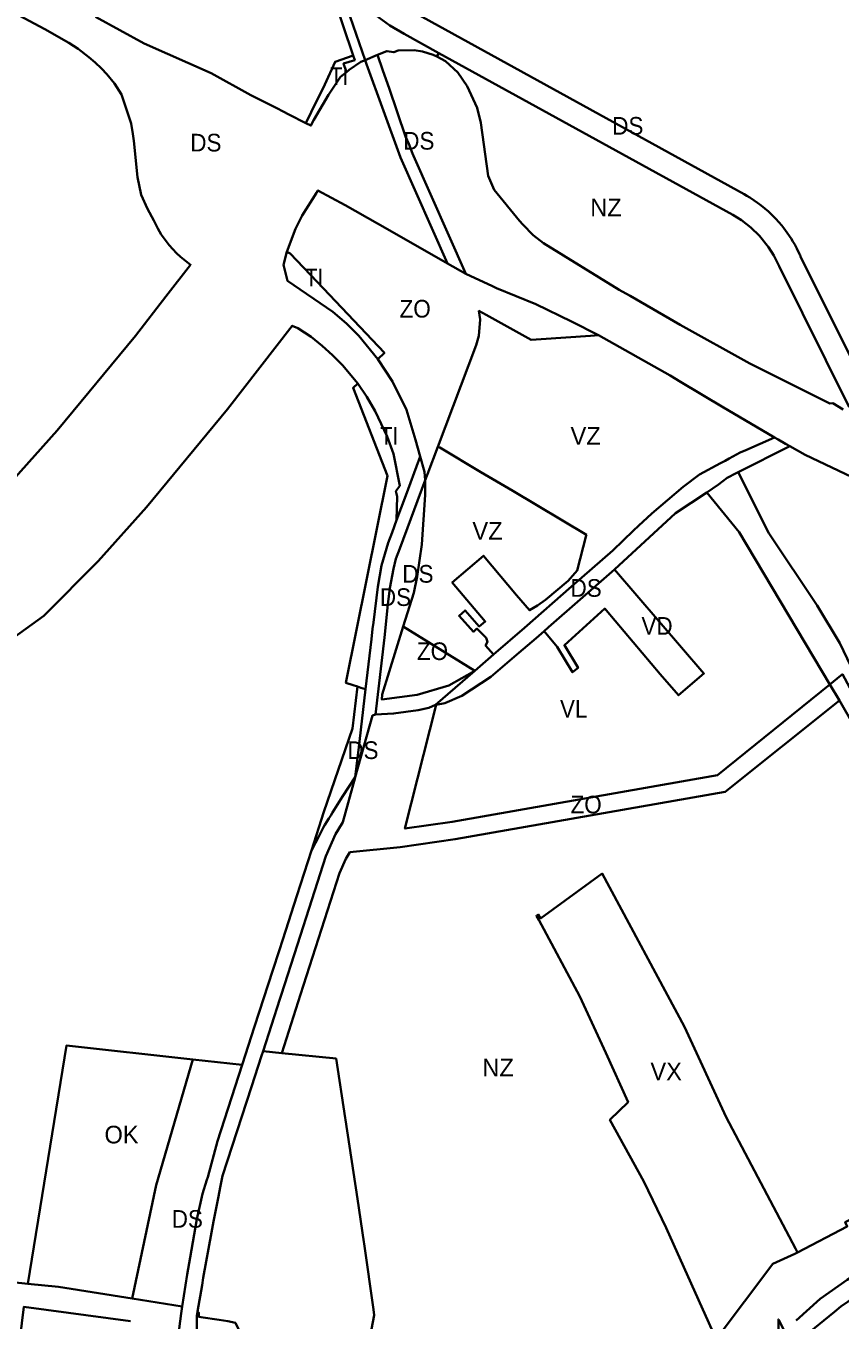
# Model space of a CAD drawing. Extents: x -650451 to -642268, y -1075216 to -1066610.
# Drawn here: x -646844 to -646153, y -1069586 to -1068487 of the extents above; entities that cross this region are included whole.
import ezdxf

# ---------------------------------------------------------------- set-up
doc = ezdxf.new("R2010")
doc.units = 0
doc.header["$LTSCALE"] = 6
doc.layers.add('1', color=7, linetype='Continuous', lineweight=35)
doc.layers.add('2', color=7, linetype='Continuous')
doc.layers.add('3', color=7, linetype='Continuous')

msp = doc.modelspace()

# ---------------------------------------------------------------- linework, layer by layer
at = {"layer": '1'}
for p, q in [((-646545.57, -1068511.42), (-646556.22, -1068515.84)), ((-646495.416, -1068512.888), (-646493.511, -1068509.855)), ((-646470.65, -1068697.38), (-646486.23, -1068688.54)), ((-646195.52, -1068843.92), (-646239.43, -1068865.79)), ((-646462.98, -1069034.61), (-646524, -1068997)), ((-646153.307, -1069059.947), (-646161.484, -1069046.228)), ((-646153.307, -1069059.947), (-646025.14, -1069285.394)), ((-646495.89, -1069063.531), (-646496.317, -1069063.61)), ((-646642.89, -1069357.68), (-646626.774, -1069359.349)), ((-646702.425, -1069364.771), (-646660.526, -1069369.36)), ((-646711.442, -1069574.759), (-646754.066, -1069567.993))]:
    msp.add_line(p, q, dxfattribs=at)
for points in [[(-646773.65, -1067792.47), (-646774.2, -1067796.04), (-646763.68, -1067804.12), (-646770.85, -1067872.24), (-646732.3, -1067997.18), (-646706.52, -1068080.45), (-646686.65, -1068143.62), (-646653.73, -1068249.25), (-646633.16, -1068315.26), (-646608.14, -1068389.1), (-646595.67, -1068425.48), (-646583.64, -1068460.55), (-646566.33, -1068512.04)], [(-646556.22, -1068515.84), (-646568.87, -1068479.14), (-646576.4, -1068457.27), (-646588.07, -1068422.96)], [(-646493.511, -1068509.855), (-646523.105, -1068493.54), (-646535.245, -1068486.342), (-646544.525, -1068479.79), (-646553.677, -1068472.283), (-646561.544, -1068464.842)], [(-646854.18, -1068475.8), (-646828.2, -1068489.61), (-646807.82, -1068501.17), (-646799.79, -1068506.39), (-646790.66, -1068513.24), (-646785.34, -1068517.77), (-646779.93, -1068522.9), (-646775.44, -1068527.74), (-646768.95, -1068535.8), (-646763.1, -1068545.18), (-646754.92, -1068569.81), (-646753.35, -1068578.6), (-646752.59, -1068584.55), (-646749.35, -1068615.18), (-646746.32, -1068630.23), (-646740.91, -1068642.34), (-646735.62, -1068652.21), (-646732.25, -1068659.06), (-646729.34, -1068663.94), (-646722.6, -1068673.11), (-646716.39, -1068679.8), (-646712.93, -1068683), (-646704.316, -1068689.698), (-646725.374, -1068716.786), (-646751.116, -1068749.975), (-646817.718, -1068830.545), (-646855.506, -1068872.883)], [(-646606.59, -1068569.33), (-646620.94, -1068561.96), (-646625.86, -1068559.47), (-646631.18, -1068556.77), (-646653.21, -1068545.58), (-646686.84, -1068526.89), (-646743.69, -1068501.76), (-646785.05, -1068479.12)], [(-646126.317, -1068803.654), (-646186.371, -1068682.825), (-646186.901, -1068681.614), (-646187.091, -1068681.19), (-646189.676, -1068675.819), (-646191.425, -1068672.562), (-646192.895, -1068670.012), (-646194.492, -1068667.409), (-646195.834, -1068665.339), (-646197.683, -1068662.645), (-646199.218, -1068660.531), (-646200.727, -1068658.552), (-646202.389, -1068656.475), (-646204.769, -1068653.669), (-646207.455, -1068650.718), (-646209.607, -1068648.501), (-646213.784, -1068644.532), (-646216.809, -1068641.902), (-646219.751, -1068639.522), (-646222.933, -1068637.129), (-646225.838, -1068635.097), (-646229.573, -1068632.68), (-646232.141, -1068631.139), (-646234.342, -1068629.892), (-646513.45, -1068476.025)], [(-646606.59, -1068569.33), (-646602.01, -1068560.15), (-646590.31, -1068536.69), (-646581.64, -1068517.24), (-646566.33, -1068512.04)], [(-646572.02, -1068526.07), (-646574.48, -1068518.75), (-646565.04, -1068515.86), (-646566.33, -1068512.04)], [(-646495.416, -1068512.888), (-646498.48, -1068511.26), (-646507.4, -1068508.45), (-646514.39, -1068507.56), (-646528.18, -1068507.58), (-646531.9, -1068509.25), (-646537.71, -1068508.16), (-646545.57, -1068511.42)], [(-646545.57, -1068511.42), (-646541.06, -1068524.58), (-646535.84, -1068539.8), (-646521.81, -1068580.69), (-646519.14, -1068587.06), (-646516.07, -1068595.08), (-646515.09, -1068597.29), (-646470.65, -1068697.38)], [(-646495.416, -1068512.888), (-646487.92, -1068516.87), (-646477.41, -1068526.45), (-646469.51, -1068538.15), (-646461.14, -1068556.34), (-646458.03, -1068569.26), (-646451.82, -1068614.31), (-646446.54, -1068626.14), (-646425.11, -1068652.37), (-646422.32, -1068655.58), (-646413.45, -1068664.71), (-646404.83, -1068671.52), (-646340.36, -1068710.915), (-646337.93, -1068712.4), (-646331.26, -1068716.25), (-646288.59, -1068740.88), (-646229.44, -1068773.53), (-646161.45, -1068807.54), (-646159.1, -1068807.43), (-646150.26, -1068812.81)], [(-646145.083, -1068810.83), (-646204.654, -1068690.937), (-646209.179, -1068681.795), (-646213.659, -1068674.696), (-646221.348, -1068665.144), (-646228.691, -1068658.051), (-646236.707, -1068651.891), (-646243.997, -1068647.407), (-646493.511, -1068509.855)], [(-646556.22, -1068515.84), (-646559.72, -1068517.29), (-646569.61, -1068524.1), (-646572.02, -1068526.07)], [(-646486.23, -1068688.54), (-646526.1, -1068598.55), (-646555, -1068519.38), (-646556.22, -1068515.84)], [(-646572.02, -1068526.07), (-646577.07, -1068530.2), (-646587.28, -1068545.28), (-646599.75, -1068566.49), (-646602.21, -1068571.5), (-646606.59, -1068569.33)], [(-646622.68, -1068678.75), (-646615.19, -1068659.11), (-646609.7, -1068647.84), (-646597.4, -1068628.74), (-646596.28, -1068626.52), (-646573.14, -1068638.98), (-646545.73, -1068654.81), (-646501.64, -1068679.81), (-646486.23, -1068688.54)], [(-646545.32, -1068769.89), (-646561.5, -1068750.22), (-646571.91, -1068739.54), (-646583.49, -1068729.76), (-646622.01, -1068703.3), (-646625.35, -1068689.7), (-646622.68, -1068678.75)], [(-646622.68, -1068678.75), (-646619.74, -1068680.15), (-646596.93, -1068704.15), (-646539.78, -1068764.65), (-646545.32, -1068769.89)], [(-646357.87, -1068749.64), (-646380.94, -1068737.81), (-646411.3, -1068723.11), (-646444.51, -1068709.64), (-646448.02, -1068707.99), (-646470.65, -1068697.38)], [(-646494.52, -1068844.29), (-646461.92, -1068757.93), (-646459.59, -1068750.19), (-646458.57, -1068736.31), (-646459.54, -1068728.94), (-646453.51, -1068732.3), (-646415.3, -1068753.62), (-646406.7, -1068753.03), (-646364.77, -1068750.16), (-646357.87, -1068749.64)], [(-646562.49, -1068790.69), (-646575.28, -1068775.04), (-646583.98, -1068766.42), (-646592.53, -1068758.66), (-646601.86, -1068751.01), (-646613.44, -1068743.65), (-646617.991, -1068741.503), (-646673.05, -1068812.491), (-646741.85, -1068895.719), (-646782.784, -1068941.581), (-646829.104, -1068987.917), (-646880.163, -1069024.903), (-646929.186, -1069052.925), (-646978.92, -1069073.93), (-647065.688, -1069087.73), (-647123.648, -1069091.043), (-647197.498, -1069094.255), (-647270.522, -1069094.255), (-647344.902, -1069091.02), (-647426.417, -1069084.624), (-647511.94, -1069076.703), (-647708.401, -1069056.275), (-647756.441, -1069053.207), (-647798.631, -1069052.508)], [(-646357.87, -1068749.64), (-646297.08, -1068783.8), (-646288.37, -1068789.04), (-646251.73, -1068811.04), (-646214.92, -1068832.85), (-646208.7, -1068836.39)], [(-646545.32, -1068769.89), (-646532.92, -1068788.95), (-646521.18, -1068812.95), (-646513.27, -1068838.37), (-646509.323, -1068852.529)], [(-646562.61, -1069048.08), (-646566.25, -1069046.92), (-646572.42, -1069044.94), (-646537.3, -1068868.95), (-646566.34, -1068794.32), (-646562.49, -1068790.69)], [(-646562.49, -1068790.69), (-646554.8, -1068801.98), (-646547.68, -1068814.22), (-646537.35, -1068835.56), (-646532.16, -1068850.47), (-646526.64, -1068877.47), (-646530.06, -1068882.16), (-646528.92, -1068886.55), (-646529.44, -1068906.81)], [(-646208.7, -1068836.39), (-646232.81, -1068847.24), (-646237.82, -1068849.24), (-646247.14, -1068854.3), (-646250.58, -1068856.16), (-646254.36, -1068858.21), (-646272.13, -1068867.84), (-646286.22, -1068878.44), (-646312.72, -1068901.07), (-646324.04, -1068911.62), (-646328.28, -1068915.58), (-646345.87, -1068932.56), (-646380.88, -1068963.08), (-646420.96, -1068998.03), (-646447.2, -1069020.9)], [(-646208.7, -1068836.39), (-646205.48, -1068838.23), (-646199.24, -1068841.79), (-646195.52, -1068843.92)], [(-646529.44, -1068906.81), (-646521.63, -1068885.74), (-646510.56, -1068855.86), (-646509.323, -1068852.529)], [(-646509.323, -1068852.529), (-646505.69, -1068865.56), (-646505.17, -1068872.78)], [(-646505.17, -1068872.78), (-646503.24, -1068867.61), (-646494.52, -1068844.29)], [(-646494.52, -1068844.29), (-646492.73, -1068845.01), (-646457.86, -1068865.8), (-646430.86, -1068881.89), (-646368.3, -1068919.19), (-646368.42, -1068919.59), (-646376.02, -1068949.34), (-646383.86, -1068958.24), (-646403.13, -1068974.41), (-646409.67, -1068979.3), (-646416.71, -1068983.21), (-646427.77, -1068970.39), (-646455.78, -1068936.87), (-646468.83, -1068948.26), (-646482.2, -1068959.52), (-646454.21, -1068992.73), (-646459.25, -1068996.98), (-646471.24, -1068983.41), (-646476.35, -1068987.98), (-646464.24, -1069001.49), (-646461.29, -1068998.81), (-646453.48, -1069006.75), (-646452.37, -1069010.01), (-646453.88, -1069013.1), (-646447.2, -1069020.9)], [(-646195.52, -1068843.92), (-646182.57, -1068851.3), (-646137.23, -1068872.6)], [(-646505.17, -1068872.78), (-646526.81, -1068930.69), (-646530.08, -1068939.43), (-646532.13, -1068948), (-646535.13, -1068964.38), (-646537.02, -1068978.44), (-646539.77, -1069006.25), (-646547.413, -1069071.71)], [(-646505.17, -1068872.78), (-646505.12, -1068885.31), (-646507.91, -1068927.47), (-646512.07, -1068954.68), (-646514.91, -1068968.48), (-646524, -1068997)], [(-646239.43, -1068865.79), (-646241.07, -1068866.67), (-646248.82, -1068870.79), (-646256.13, -1068876.42), (-646266.118, -1068883.048)], [(-646239.43, -1068865.79), (-646213.25, -1068917.87), (-646172.32, -1068979.11), (-646153.2, -1069011.21), (-646103.59, -1069114.91)], [(-646266.118, -1068883.048), (-646292.75, -1068900.72), (-646344.49, -1068948.736)], [(-646161.484, -1069046.228), (-646238.632, -1068916.799), (-646266.118, -1068883.048)], [(-646555.84, -1069050.22), (-646550.89, -1069007.7), (-646549.81, -1068998.88), (-646549.17, -1068993.71), (-646545.42, -1068963.3), (-646542.16, -1068945.12), (-646536.54, -1068925.95), (-646533.28, -1068917.17), (-646529.44, -1068906.81)], [(-646404.269, -1069001.033), (-646400.39, -1068997.58), (-646344.49, -1068948.736)], [(-646344.49, -1068948.736), (-646268.528, -1069036.82), (-646290.099, -1069055.423), (-646305.65, -1069037.39), (-646351.641, -1068983.083), (-646351.638, -1068983.08), (-646352.71, -1068981.82), (-646386.936, -1069012.936), (-646375.346, -1069032.07), (-646379.973, -1069035.889), (-646393.09, -1069014.234), (-646404.269, -1069001.033)], [(-646524, -1068997), (-646541.71, -1069054.76), (-646542, -1069059), (-646512, -1069055), (-646485, -1069047), (-646462.98, -1069034.61)], [(-646404.269, -1069001.033), (-646410.96, -1069006.99), (-646425.52, -1069019.41), (-646449.419, -1069039.805), (-646474.13, -1069055.83), (-646488.537, -1069062.169), (-646495.89, -1069063.531)], [(-646496.317, -1069063.61), (-646462.98, -1069034.61), (-646447.2, -1069020.9)], [(-646017.15, -1069280.19), (-646037.99, -1069242.88), (-646107, -1069119.41), (-646150.87, -1069037.64), (-646152.26, -1069038.76), (-646161.484, -1069046.228)], [(-646601.82, -1069187.25), (-646591.26, -1069154.54), (-646566.82, -1069083.62), (-646562.61, -1069048.08)], [(-646564.54, -1069125.08), (-646562.35, -1069106.21), (-646561.88, -1069102.18), (-646555.84, -1069050.22)], [(-646562.61, -1069048.08), (-646559.8, -1069048.98), (-646555.84, -1069050.22)], [(-646495.89, -1069063.531), (-646522.35, -1069168.648), (-646482.211, -1069162.813), (-646256.824, -1069123.414), (-646161.484, -1069046.228)], [(-646153.307, -1069059.947), (-646250.409, -1069137.52), (-646479.84, -1069177.626), (-646526.31, -1069184.381), (-646569.114, -1069188.86), (-646572.586, -1069194.485), (-646577.878, -1069206.485), (-646611.107, -1069309.68), (-646626.774, -1069359.349)], [(-646547.413, -1069071.71), (-646549.91, -1069072.542), (-646564.54, -1069125.08)], [(-646496.317, -1069063.61), (-646502, -1069066), (-646511, -1069068), (-646532, -1069071), (-646547.413, -1069071.71)], [(-646564.54, -1069125.08), (-646564.605, -1069125.271), (-646575.015, -1069163.152), (-646575.87, -1069164.54), (-646581.29, -1069173.32), (-646589.56, -1069192.07), (-646601.41, -1069229.34), (-646613.6, -1069267.04), (-646627.59, -1069310.34), (-646628.66, -1069313.66), (-646642.89, -1069357.68)], [(-646564.54, -1069125.08), (-646575.4, -1069141.46), (-646582.46, -1069152.81), (-646583.89, -1069155.1), (-646585.42, -1069157.56), (-646586.97, -1069160.06), (-646590.38, -1069165.55), (-646591.4, -1069167.48), (-646595.32, -1069174.92), (-646601.82, -1069187.25)], [(-646601.82, -1069187.25), (-646614.05, -1069225.78), (-646626.03, -1069262.8), (-646629.14, -1069272.42), (-646634.5, -1069288.96), (-646650.036, -1069336.95), (-646660.526, -1069369.36)], [(-646189.17, -1069528.74), (-646190.68, -1069525.54), (-646249.6, -1069413.93), (-646284.98, -1069337.17), (-646354.82, -1069206.96), (-646407.33, -1069245.03), (-646409.21, -1069241.71), (-646410.74, -1069242.8), (-646408.81, -1069246.1), (-646373.91, -1069311.42), (-646351.69, -1069359.26), (-646332.84, -1069401.02), (-646348.36, -1069416.16), (-646319.61, -1069468.58), (-646300.42, -1069507.93), (-646258.086, -1069602.285)], [(-646702.425, -1069364.771), (-646809.879, -1069353.002), (-646842.441, -1069555.283)], [(-646698.4, -1069578.93), (-646694.47, -1069556.69), (-646693.58, -1069550.28), (-646686.56, -1069511.7), (-646684.95, -1069502.53), (-646680.77, -1069481.22), (-646679.13, -1069473.51), (-646677.18, -1069463.79), (-646652.72, -1069388.08), (-646644.22, -1069361.78), (-646642.89, -1069357.68)], [(-646626.774, -1069359.349), (-646580.797, -1069364.111), (-646573.08, -1069414.47), (-646572.86, -1069416.23), (-646562.65, -1069483.12), (-646557.39, -1069519.61), (-646557.09, -1069521.46), (-646549.097, -1069577.256), (-646548.41, -1069582.03), (-646550.76, -1069593.9), (-646560.5, -1069643.52), (-646569.86, -1069690.67), (-646581.489, -1069759.421)], [(-646702.425, -1069364.771), (-646733.74, -1069471.688), (-646754.066, -1069567.993)], [(-646660.526, -1069369.36), (-646681.5, -1069434.17), (-646689.8, -1069464.71), (-646690.51, -1069466.97), (-646694.26, -1069478.99), (-646699.07, -1069500.57), (-646704.68, -1069533.06), (-646707.16, -1069547.44), (-646711.442, -1069574.759)], [(-646189.17, -1069528.74), (-646146.8, -1069506.6), (-646148.5, -1069503), (-646102.15, -1069479.49), (-646080.35, -1069469.89), (-646028.16, -1069441.58), (-646023.96, -1069440.34)], [(-646017.63, -1069499.08), (-646020.75, -1069500), (-646075.48, -1069516.38), (-646094.39, -1069523.34), (-646112.56, -1069531.78), (-646129.87, -1069541.19), (-646146.81, -1069551.97), (-646169.9, -1069568.04), (-646190.07, -1069586.48)], [(-646265.02, -1069696.43), (-646263.66, -1069694.78), (-646244.03, -1069670.61), (-646232.98, -1069657.69), (-646203.35, -1069617.55), (-646197.52, -1069612.3), (-646186.23, -1069623.04), (-646193.38, -1069608.83), (-646183.24, -1069600.22), (-646157.69, -1069579.08), (-646152.27, -1069574.59), (-646128.27, -1069558.17), (-646091.98, -1069538.88), (-646085.67, -1069536.53), (-646056.24, -1069525.54), (-646018.55, -1069514.14)], [(-647608.81, -1069551.868), (-647567.252, -1069548.083), (-647434.969, -1069537.141), (-647341.697, -1069532.602), (-647204.293, -1069530.647), (-647140.008, -1069530.068), (-647046.325, -1069533.275), (-646986.633, -1069539.757), (-646842.441, -1069555.283)], [(-646258.086, -1069602.285), (-646209.9, -1069538.5), (-646191.4, -1069529.9), (-646189.17, -1069528.74)], [(-646842.441, -1069555.283), (-646816.615, -1069558.064), (-646754.066, -1069567.993)], [(-646755.269, -1069587.04), (-646846, -1069575), (-646862.955, -1069713.633)], [(-646711.442, -1069574.759), (-646712.34, -1069580.49), (-646714.037, -1069593.585)], [(-646703.88, -1069739.43), (-646702.67, -1069737.03), (-646700.97, -1069703.95), (-646699.78, -1069680.46), (-646699.3, -1069672.67), (-646698.64, -1069658.79), (-646698.34, -1069652.98), (-646698.96, -1069582.26), (-646698.4, -1069578.93)], [(-646698.4, -1069578.93), (-646697.31, -1069579.97), (-646697.31, -1069583.47), (-646695.61, -1069583.8), (-646695.65, -1069583.72), (-646680.25, -1069585.99), (-646672.68, -1069587.24), (-646666.36, -1069588.57), (-646659.83, -1069601.8), (-646659.52, -1069605.53), (-646659.65, -1069605.99), (-646662.57, -1069621.66), (-646666.26, -1069641.2), (-646671.69, -1069669.92), (-646673, -1069676.8), (-646678.52, -1069705.63), (-646680.28, -1069714.83), (-646677.36, -1069733.65), (-646679.46, -1069745.37)], [(-646198.82, -1069597.83), (-646205.25, -1069585.67), (-646205, -1069606.03)]]:
    msp.add_lwpolyline(points, dxfattribs=at)

# ---------------------------------------------------------------- texts
at = {"layer": '2', "width": 0.95}
for s, p in [('DS', (-646523.808, -1068591.918)), ('DS', (-646381.748, -1068971.795)), ('DS', (-646543.626, -1068979.574)), ('VD', (-646321.525, -1069003.999))]:
    msp.add_text(s, height=15, dxfattribs=at).set_placement(p)
at = {"layer": '2'}
for s, p in [('NZ', (-646365.033, -1068648.489)), ('VZ', (-646381.736, -1068842.633)), ('NZ', (-646456.654, -1069379.245)), ('VX', (-646313.929, -1069382.496))]:
    msp.add_text(s, height=15, dxfattribs=at).set_placement(p)
at = {"layer": '3'}
for s, width, p in [('TI', 0.85, (-646585.802, -1068536.936)), ('DS', 0.95, (-646346.361, -1068579.22)), ('DS', 0.95, (-646704.63, -1068593.488)), ('TI', 0.85, (-646606.995, -1068708.002)), ('ZO', 0.95, (-646526.91, -1068734.573)), ('TI', 0.85, (-646543.389, -1068842.527)), ('DS', 0.95, (-646524.593, -1068959.783)), ('ZO', 0.95, (-646512.185, -1069025.521)), ('VL', 0.95, (-646390.722, -1069074.354)), ('DS', 0.95, (-646571.277, -1069109.575)), ('ZO', 0.95, (-646381.733, -1069155.787)), ('DS', 0.95, (-646720.386, -1069507.782))]:
    msp.add_text(s, height=15, dxfattribs=dict(at, width=width)).set_placement(p)
for s, p in [('VZ', (-646465.091, -1068923.31)), ('OK', (-646777.5, -1069436.142))]:
    msp.add_text(s, height=15, dxfattribs=at).set_placement(p)

doc.saveas('drawing.dxf')
